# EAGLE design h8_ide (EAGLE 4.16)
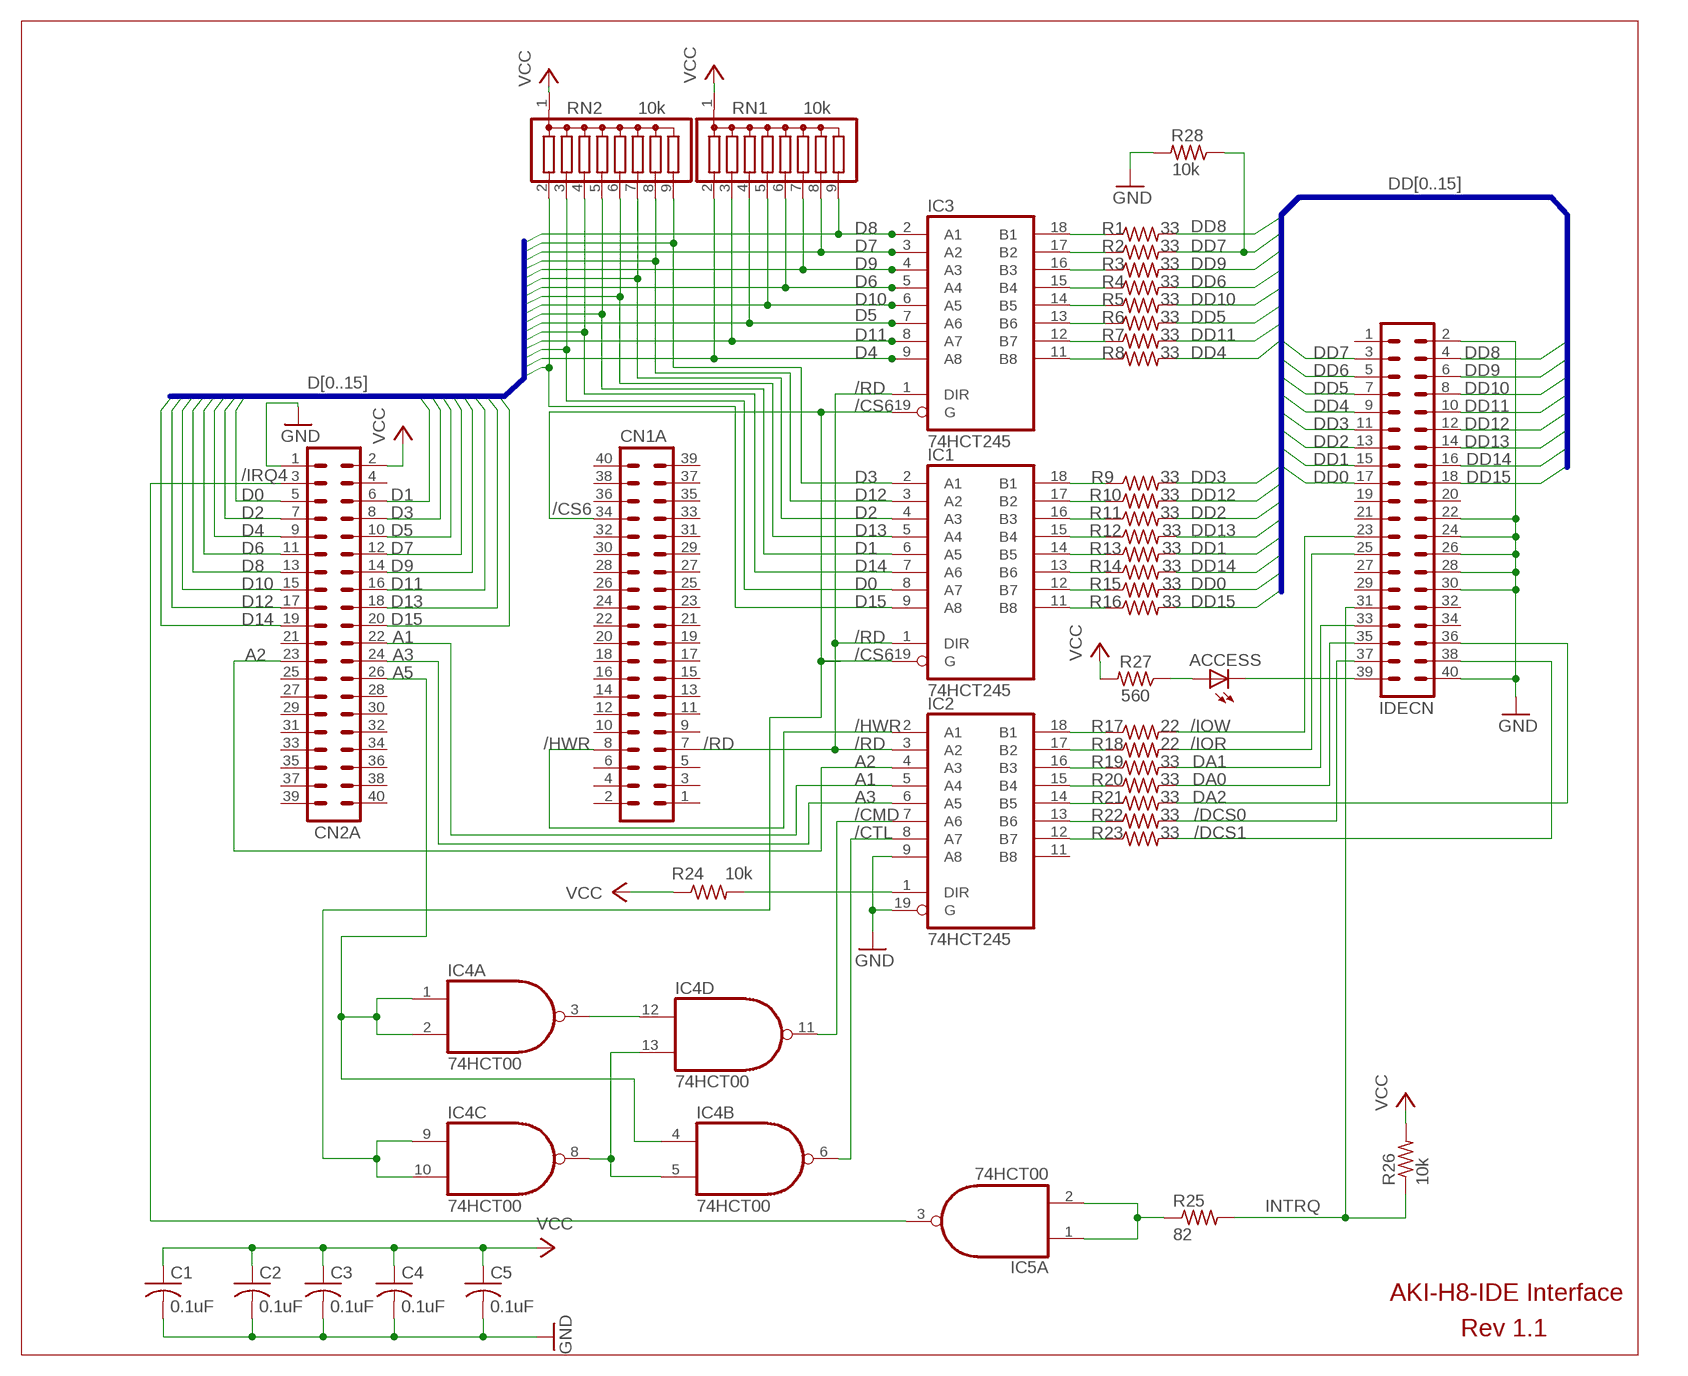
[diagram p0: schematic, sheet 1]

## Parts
ACCESS  LED3MM  [LED3MM]
C1  0.1uF  C-US025-024X044  [C025-024X044]
C2  0.1uF  C-US025-024X044  [C025-024X044]
C3  0.1uF  C-US025-024X044  [C025-024X044]
C4  0.1uF  C-US025-024X044  [C025-024X044]
C5  0.1uF  C-US025-024X044  [C025-024X044]
CN1A  MA20-2  [MA20-2]
CN2A  MA20-2  [MA20-2]
IC1  74HCT245  74LS245N  [DIL20]
IC2  74HCT245  74LS245N  [DIL20]
IC3  74HCT245  74LS245N  [DIL20]
IC4  74HCT00  7400N  [DIL14]
IC5  74HCT00  7400N  [DIL14]
IDECN  MA20-2  [MA20-2]
R1  33  R-US_0204/5  [0204/5]
R2  33  R-US_0204/5  [0204/5]
R3  33  R-US_0204/5  [0204/5]
R4  33  R-US_0204/5  [0204/5]
R5  33  R-US_0204/5  [0204/5]
R6  33  R-US_0204/5  [0204/5]
R7  33  R-US_0204/5  [0204/5]
R8  33  R-US_0204/5  [0204/5]
R9  33  R-US_0204/5  [0204/5]
R10  33  R-US_0204/5  [0204/5]
R11  33  R-US_0204/5  [0204/5]
R12  33  R-US_0204/5  [0204/5]
R13  33  R-US_0204/5  [0204/5]
R14  33  R-US_0204/5  [0204/5]
R15  33  R-US_0204/5  [0204/5]
R16  33  R-US_0204/5  [0204/5]
R17  22  R-US_0204/5  [0204/5]
R18  22  R-US_0204/5  [0204/5]
R19  33  R-US_0204/5  [0204/5]
R20  33  R-US_0204/5  [0204/5]
R21  33  R-US_0204/5  [0204/5]
R22  33  R-US_0204/5  [0204/5]
R23  33  R-US_0204/5  [0204/5]
R24  10k  R-US_0204/5  [0204/5]
R25  82  R-US_0204/5  [0204/5]
R26  10k  R-US_0204/5  [0204/5]
R27  560  R-US_0204/5  [0204/5]
R28  10k  R-US_0204/5  [0204/5]
RN1  10k  G08R  [SIL9]
RN2  10k  G08R  [SIL9]

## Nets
/CMD: IC2.7(A6) IC4.11(D:O)
/CS6: CN1A.34 IC1.19(G) IC3.19(G) IC4.9(C:I0) IC4.10(C:I1)
/CTL: IC2.8(A7) IC4.6(B:O)
/DCS0: IDECN.37 R22.2
/DCS1: IDECN.38 R23.2
/HWR: CN1A.8 IC2.2(A1)
/IOR: IDECN.25 R18.2
/IOW: IDECN.23 R17.2
/IRQ4: CN2A.3 IC5.3(A:O)
/RD: CN1A.7 IC1.1(DIR) IC2.3(A2) IC3.1(DIR)
A1: CN2A.22 IC2.5(A4)
A2: CN2A.23 IC2.4(A3)
A3: CN2A.24 IC2.6(A5)
A5: CN2A.26 IC4.1(A:I0) IC4.2(A:I1) IC4.4(B:I0)
D0: CN2A.5 IC1.8(A7) RN2.3
D1: CN2A.6 IC1.6(A5) RN2.5
D2: CN2A.7 IC1.4(A3) RN2.7
D3: CN2A.8 IC1.2(A1) RN2.9
D4: CN2A.9 IC3.9(A8) RN1.2
D5: CN2A.10 IC3.7(A6) RN1.4
D6: CN2A.11 IC3.5(A4) RN1.6
D7: CN2A.12 IC3.3(A2) RN1.8
D8: CN2A.13 IC3.2(A1) RN1.9
D9: CN2A.14 IC3.4(A3) RN1.7
D10: CN2A.15 IC3.6(A5) RN1.5
D11: CN2A.16 IC3.8(A7) RN1.3
D12: CN2A.17 IC1.3(A2) RN2.8
D13: CN2A.18 IC1.5(A4) RN2.6
D14: CN2A.19 IC1.7(A6) RN2.4
D15: CN2A.20 IC1.9(A8) RN2.2
DA0: IDECN.35 R20.2
DA1: IDECN.33 R19.2
DA2: IDECN.36 R21.2
DD0: IDECN.17 R15.2
DD1: IDECN.15 R13.2
DD2: IDECN.13 R11.2
DD3: IDECN.11 R9.2
DD4: IDECN.9 R8.2
DD5: IDECN.7 R6.2
DD6: IDECN.5 R4.2
DD7: IDECN.3 R2.2 R28.1
DD8: IDECN.4 R1.2
DD9: IDECN.6 R3.2
DD10: IDECN.8 R5.2
DD11: IDECN.10 R7.2
DD12: IDECN.12 R10.2
DD13: IDECN.14 R12.2
DD14: IDECN.16 R14.2
DD15: IDECN.18 R16.2
GND: C1.2 C2.2 C3.2 C4.2 C5.2 CN2A.1 IC2.9(A8) IC2.19(G) IDECN.2 IDECN.22 IDECN.24 IDECN.26 IDECN.28 IDECN.30 IDECN.40 R28.2
INTRQ: IDECN.31 R25.2 R26.1
N$1: IC3.18(B1) R1.1
N$2: IC3.17(B2) R2.1
N$3: IC3.16(B3) R3.1
N$4: IC3.15(B4) R4.1
N$5: IC3.14(B5) R5.1
N$6: IC3.13(B6) R6.1
N$7: IC3.12(B7) R7.1
N$8: IC3.11(B8) R8.1
N$9: IC1.18(B1) R9.1
N$10: IC1.17(B2) R10.1
N$11: IC1.16(B3) R11.1
N$12: IC1.15(B4) R12.1
N$13: IC1.14(B5) R13.1
N$14: IC1.13(B6) R14.1
N$15: IC1.12(B7) R15.1
N$16: IC1.11(B8) R16.1
N$17: IC2.18(B1) R17.1
N$18: IC2.17(B2) R18.1
N$19: IC2.16(B3) R19.1
N$20: IC2.15(B4) R20.1
N$21: IC2.14(B5) R21.1
N$22: IC2.13(B6) R22.1
N$23: IC2.12(B7) R23.1
N$26: ACCESS.K(C) IDECN.39
N$27: ACCESS.A R27.1
N$29: IC2.1(DIR) R24.2
N$30: IC4.5(B:I1) IC4.8(C:O) IC4.13(D:I1)
N$32: IC4.3(A:O) IC4.12(D:I0)
N$33: IC5.1(A:I0) IC5.2(A:I1) R25.1
VCC: C1.1 C2.1 C3.1 C4.1 C5.1 CN2A.2 R24.1 R26.2 R27.2 RN1.1 RN2.1
Unconnected: CN1A.1 CN1A.2 CN1A.3 CN1A.4 CN1A.5 CN1A.6 CN1A.9 CN1A.10 CN1A.11 CN1A.12 CN1A.13 CN1A.14 CN1A.15 CN1A.16 CN1A.17 CN1A.18 CN1A.19 CN1A.20 CN1A.21 CN1A.22 CN1A.23 CN1A.24 CN1A.25 CN1A.26 CN1A.27 CN1A.28 CN1A.29 CN1A.30 CN1A.31 CN1A.32 CN1A.33 CN1A.35 CN1A.36 CN1A.37 CN1A.38 CN1A.39 CN1A.40 CN2A.4 CN2A.21 CN2A.25 CN2A.27 CN2A.28 CN2A.29 CN2A.30 CN2A.31 CN2A.32 CN2A.33 CN2A.34 CN2A.35 CN2A.36 CN2A.37 CN2A.38 CN2A.39 CN2A.40 IC2.11(B8) IC5.4(B:I0) IC5.5(B:I1) IC5.6(B:O) IC5.8(C:O) IC5.9(C:I0) IC5.10(C:I1) IC5.11(D:O) IC5.12(D:I0) IC5.13(D:I1) IDECN.1 IDECN.19 IDECN.20 IDECN.21 IDECN.27 IDECN.29 IDECN.32 IDECN.34

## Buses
D[0..15]
DD[0..15]

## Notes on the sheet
- AKI-H8-IDE Interface
- Rev 1.1

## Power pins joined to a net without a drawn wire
GND: IC1.10(GND) IC2.10(GND) IC3.10(GND) IC4.7(P:GND) IC5.7(P:GND)
VCC: IC1.20(VCC) IC2.20(VCC) IC3.20(VCC) IC4.14(P:VCC) IC5.14(P:VCC)

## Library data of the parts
ACCESS = led:LED: LED
C1-C5 = rcl:C-US: CAPACITOR, American symbol
CN1A CN2A IDECN = con-lstb:MA20-2: PIN HEADER
IC1-IC3 = 74xx-us:74*245: Octal BUS TRANSCEIVER, 3-state
IC4 IC5 = 74xx-us:74*00: Quad 2-input NAND gate
R1-R28 = rcl:R-US_: RESISTOR, American symbol
RN1 RN2 = resistor-sil:G08R: SIL RESISTOR

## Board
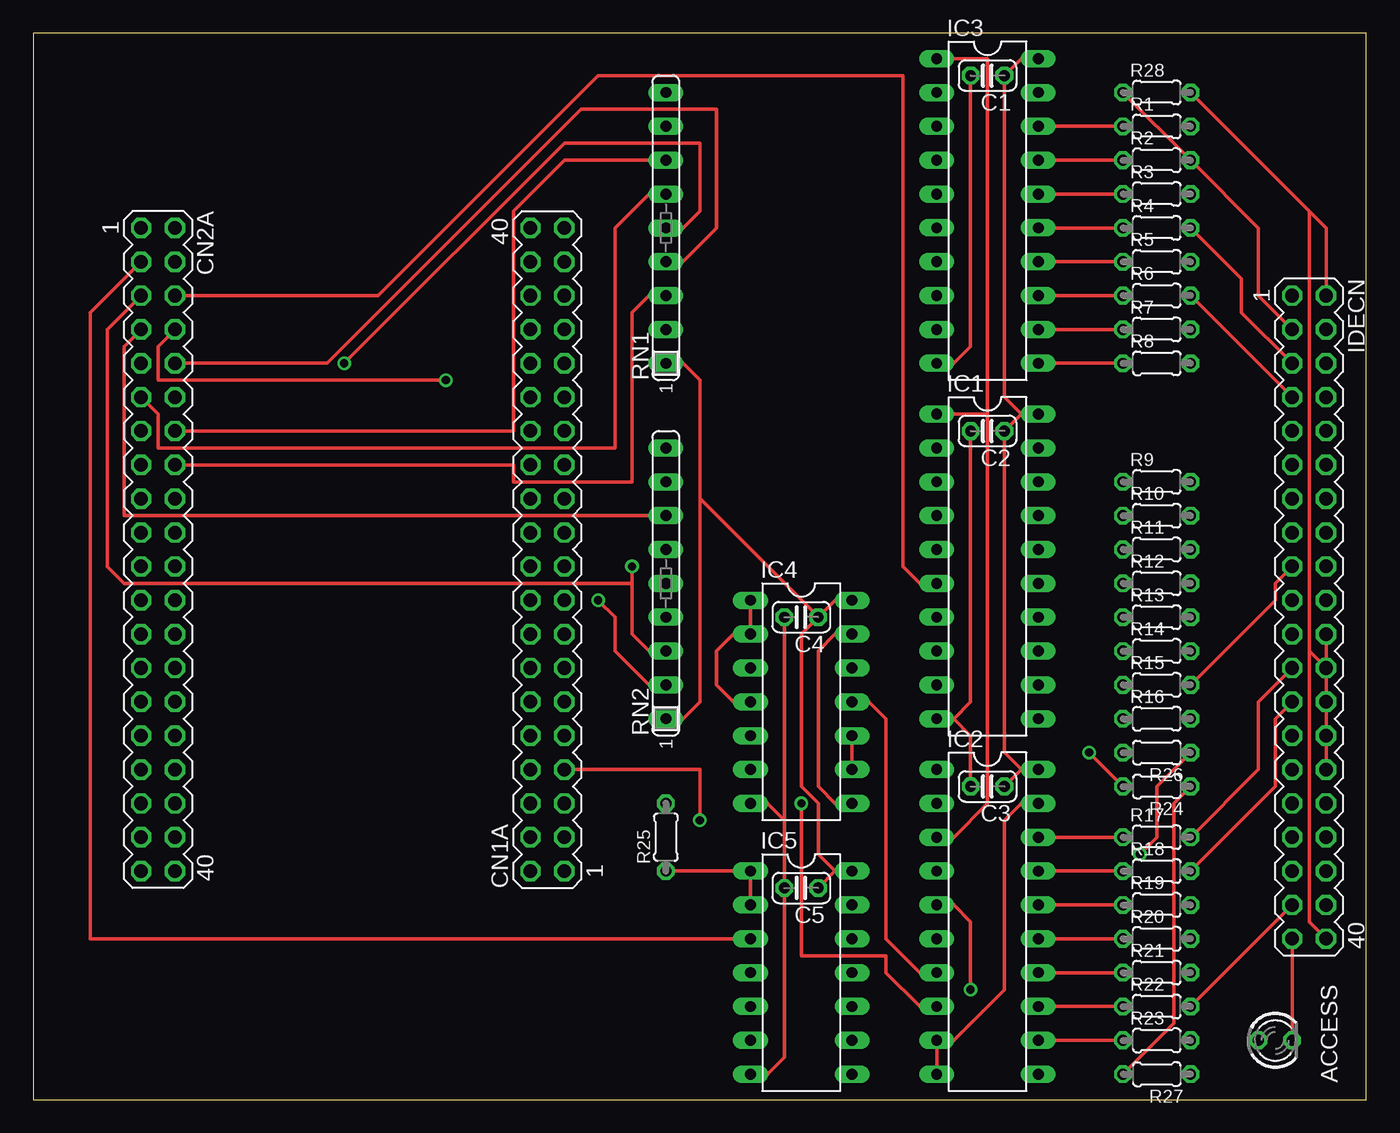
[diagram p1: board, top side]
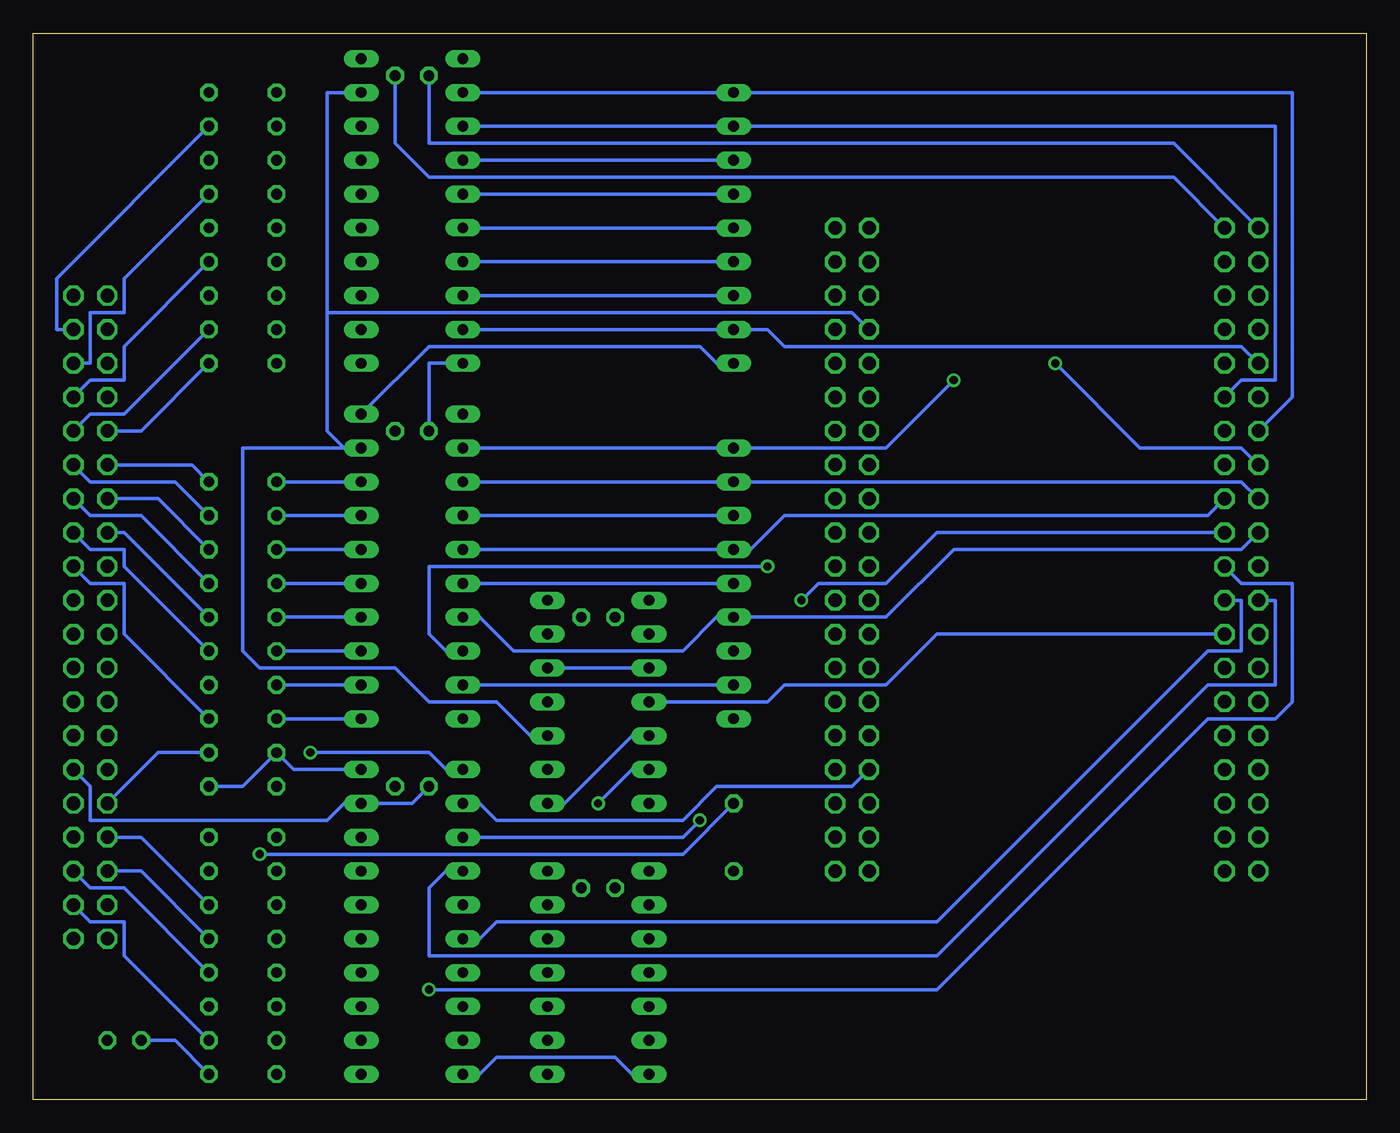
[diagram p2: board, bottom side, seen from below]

Size 100 x 80 mm. Coordinates in mm from the lower left corner, seen from the top.
Outline: 0,0 100,0 100,80 0,80 0,0
Copper layers (1*16): Top 0.035mm / dielectric 1.5mm / Bottom 0.035mm
Design rules "default": minimum track width 10mil, minimum drill 24mil, track to track 8mil, track to pad 8mil, pad to pad 8mil, via to via 8mil, smd to smd 8mil, copper to edge 40mil, drill to drill 8mil, minimum pad ring 10mil, minimum via ring 8mil, stop-mask expansion 4mil, vias tented up to drill 0mil, thermal gap 10mil

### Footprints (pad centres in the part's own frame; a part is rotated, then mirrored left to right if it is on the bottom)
LED3MM = drill 0.813 octagon: A -1.27,0; K 1.27,0
C025-024X044 = drill 0.813 octagon: 1 -1.27,0; 2 1.27,0
MA20-2 = drill 1.016 octagon: 1 -24.13,-1.27; 2 -24.13,1.27; 3 -21.59,-1.27; 4 -21.59,1.27; 5 -19.05,-1.27; 6 -19.05,1.27; 7 -16.51,-1.27; 8 -16.51,1.27; 9 -13.97,-1.27; 10 -13.97,1.27; 11 -11.43,-1.27; 12 -11.43,1.27; 13 -8.89,-1.27; 14 -8.89,1.27; 15 -6.35,-1.27; 16 -6.35,1.27; 17 -3.81,-1.27; 18 -3.81,1.27; 19 -1.27,-1.27; 20 -1.27,1.27; 21 1.27,-1.27; 22 1.27,1.27; 23 3.81,-1.27; 24 3.81,1.27; 25 6.35,-1.27; 26 6.35,1.27; 27 8.89,-1.27; 28 8.89,1.27; 29 11.43,-1.27; 30 11.43,1.27; 31 13.97,-1.27; 32 13.97,1.27; 33 16.51,-1.27; 34 16.51,1.27; 35 19.05,-1.27; 36 19.05,1.27; 37 21.59,-1.27; 38 21.59,1.27; 39 24.13,-1.27; 40 24.13,1.27
DIL20 = drill 0.813 long: 1 -11.43,-3.81; 2 -8.89,-3.81; 3 -6.35,-3.81; 4 -3.81,-3.81; 5 -1.27,-3.81; 6 1.27,-3.81; 7 3.81,-3.81; 8 6.35,-3.81; 9 8.89,-3.81; 10 11.43,-3.81; 11 11.43,3.81; 12 8.89,3.81; 13 6.35,3.81; 14 3.81,3.81; 15 1.27,3.81; 16 -1.27,3.81; 17 -3.81,3.81; 18 -6.35,3.81; 19 -8.89,3.81; 20 -11.43,3.81
DIL14 = drill 0.813 long: 1 -7.62,-3.81; 2 -5.08,-3.81; 3 -2.54,-3.81; 4 0,-3.81; 5 2.54,-3.81; 6 5.08,-3.81; 7 7.62,-3.81; 8 7.62,3.81; 9 5.08,3.81; 10 2.54,3.81; 11 0,3.81; 12 -2.54,3.81; 13 -5.08,3.81; 14 -7.62,3.81
0204/5 = drill 0.813 octagon: 1 -2.54,0; 2 2.54,0
SIL9 = drill 0.813 long: 1 -10.16,0; 2 -7.62,0; 3 -5.08,0; 4 -2.54,0; 5 0,0; 6 2.54,0; 7 5.08,0; 8 7.62,0; 9 10.16,0

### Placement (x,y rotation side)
ACCESS  93.18,4.44 0 top
C1  71.59,76.83 180 top
C2  71.59,50.16 180 top
C3  71.59,23.49 180 top
C4  57.62,36.19 180 top
C5  57.62,15.87 180 top
CN1A  38.57,41.27 90 top
CN2A  9.36,41.27 270 top
IC1  71.59,40 270 top
IC2  71.59,13.33 270 top
IC3  71.59,66.67 270 top
IC4  57.62,29.84 270 top
IC5  57.62,9.52 270 top
IDECN  95.72,36.19 270 top
R1  84.29,73.02 0 top
R2  84.29,70.48 0 top
R3  84.29,67.94 0 top
R4  84.29,65.4 0 top
R5  84.29,62.86 0 top
R6  84.29,60.32 0 top
R7  84.29,57.78 0 top
R8  84.29,55.24 0 top
R9  84.29,46.35 0 top
R10  84.29,43.81 0 top
R11  84.29,41.27 0 top
R12  84.29,38.73 0 top
R13  84.29,36.19 0 top
R14  84.29,33.65 0 top
R15  84.29,31.11 0 top
R16  84.29,28.57 0 top
R17  84.29,19.68 0 top
R18  84.29,17.14 0 top
R19  84.29,14.6 0 top
R20  84.29,12.06 0 top
R21  84.29,9.52 0 top
R22  84.29,6.98 0 top
R23  84.29,4.44 0 top
R24  84.29,23.49 180 top
R25  47.46,19.68 90 top
R26  84.29,26.03 180 top
R27  84.29,1.9 180 top
R28  84.29,75.56 0 top
RN1  47.46,65.4 90 top
RN2  47.46,38.73 90 top

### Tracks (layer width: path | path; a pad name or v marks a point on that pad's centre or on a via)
/CMD
  Top 0.254: IC2.7 66.51,9.52 63.97,12.06 63.97,28.57 62.7,29.84 IC4.11
/CS6
  Top 0.254: IC4.9 IC4.10
  Bottom 0.254: 76.67,48.89 77.94,50.16 77.94,59.05 | 77.94,59.05 77.94,75.56 IC3.19 | CN1A.34 38.57,59.05 77.94,59.05 | 76.67,48.89 84.29,48.89 84.29,33.65 83.02,32.38 72.86,32.38 70.32,29.84 65.24,29.84 62.7,27.3 IC4.10 | 76.67,48.89 IC1.19
/CTL  (via drill 0.61)
  Top 0.254: v57.62,22.22 57.62,10.79 63.97,10.79 63.97,9.52 66.51,6.98 IC2.8
  Bottom 0.254: v57.62,22.22 55.08,24.76 IC4.6
/DCS0
  Top 0.254: R22.2 IDECN.37
/DCS1
  Bottom 0.254: R23.2 93.18,10.79 93.18,13.33 95.72,13.33 IDECN.38
/HWR
  Bottom 0.254: CN1A.8 38.57,23.49 48.73,23.49 51.27,20.95 65.24,20.95 66.51,22.22 IC2.2
/IOR
  Top 0.254: R18.2 93.18,23.49 93.18,28.57 IDECN.25
/IOW
  Top 0.254: R17.2 91.91,24.76 91.91,29.84 IDECN.23
/IRQ4
  Top 0.254: CN2A.3 4.28,59.05 4.28,12.06 IC5.3
/RD  (via drill 0.61)
  Top 0.254: 71.59,51.43 71.59,22.22 69.05,19.68 IC2.3 | 71.59,51.43 IC1.1 | 71.59,51.43 71.59,78.1 IC3.1 | CN1A.7 50,24.76 v50,20.95
  Bottom 0.254: v50,20.95 51.27,19.68 IC2.3
A1  (via drill 0.61)
  Top 0.254: v70.32,8.25 70.32,13.33 69.05,14.6 IC2.5
  Bottom 0.254: v70.32,8.25 32.22,8.25 11.9,28.57 6.82,28.57 5.55,29.84 5.55,38.73 9.36,38.73 CN2A.22
A2
  Bottom 0.254: CN2A.23 6.82,37.46 6.82,31.11 11.9,31.11 32.22,10.79 70.32,10.79 70.32,15.87 69.05,17.14 IC2.4
A3
  Bottom 0.254: CN2A.24 9.36,37.46 9.36,33.65 11.9,33.65 32.22,13.33 65.24,13.33 66.51,12.06 IC2.6
A5
  Top 0.254: IC4.4 52.54,29.84 51.27,31.11 51.27,33.65 52.54,34.92 IC4.2 IC4.1
  Bottom 0.254: CN2A.26 32.22,34.92 36.03,31.11 43.65,31.11 44.92,29.84 IC4.4
D0  (via drill 0.61)
  Top 0.254: CN2A.5 5.55,57.78 5.55,40 6.82,38.73 44.92,38.73 | 44.92,38.73 44.92,34.92 46.19,33.65 RN2.3 | 44.92,38.73 v44.92,40
  Bottom 0.254: v44.92,40 70.32,40 70.32,34.92 69.05,33.65 IC1.8
D1
  Top 0.254: CN2A.6 25.87,60.32 42.38,76.83 65.24,76.83 65.24,40 66.51,38.73 IC1.6
  Bottom 0.254: IC1.6 RN2.5
D2
  Top 0.254: CN2A.7 6.82,56.51 6.82,43.81 RN2.7
  Bottom 0.254: RN2.7 IC1.4
D3  (via drill 0.61)
  Top 0.254: CN2A.8 9.36,56.51 9.36,53.97 v30.95,53.97
  Bottom 0.254: IC1.2 RN2.9 36.03,48.89 v30.95,53.97
D4
  Bottom 0.254: CN2A.9 9.36,56.51 43.65,56.51 44.92,57.78 RN1.2 IC3.9
D5
  Top 0.254: CN2A.10 22.06,55.24 41.11,74.29 51.27,74.29 51.27,65.4 48.73,62.86 RN1.4
  Bottom 0.254: RN1.4 IC3.7
D6
  Top 0.254: CN2A.11 9.36,51.43 9.36,48.89 43.65,48.89 43.65,65.4 46.19,67.94 RN1.6
  Bottom 0.254: RN1.6 IC3.5
D7
  Bottom 0.254: CN2A.12 9.36,53.97 6.82,53.97 6.82,73.02 RN1.8 IC3.3
D8
  Bottom 0.254: CN2A.13 5.55,52.7 5.55,75.56 RN1.9 IC3.2
D9
  Top 0.254: CN2A.14 36.03,50.16 36.03,66.67 39.84,70.48 RN1.7
  Bottom 0.254: RN1.7 IC3.4
D10  (via drill 0.61)
  Top 0.254: v23.33,55.24 39.84,71.75 50,71.75 50,66.67 48.73,65.4 RN1.5
  Bottom 0.254: RN1.5 IC3.6 | CN2A.15 9.36,48.89 16.98,48.89 v23.33,55.24
D11
  Top 0.254: CN2A.16 36.03,47.62 36.03,46.35 44.92,46.35 44.92,59.05 46.19,60.32 RN1.3
  Bottom 0.254: RN1.3 IC3.8
D12
  Bottom 0.254: CN2A.17 9.36,46.35 RN2.8 IC1.3
D13
  Bottom 0.254: CN2A.18 11.9,43.81 43.65,43.81 46.19,41.27 RN2.6 IC1.5
D14
  Bottom 0.254: IC1.7 66.51,36.19 63.97,33.65 51.27,33.65 48.73,36.19 RN2.4 36.03,36.19 30.95,41.27 9.36,41.27 CN2A.19
D15  (via drill 0.61)
  Top 0.254: v42.38,37.46 43.65,36.19 43.65,33.65 46.19,31.11 RN2.2
  Bottom 0.254: CN2A.20 32.22,42.54 36.03,38.73 41.11,38.73 v42.38,37.46 | RN2.2 IC1.9
DA0
  Bottom 0.254: R20.2 91.91,17.14 IDECN.35
DA1
  Bottom 0.254: R19.2 91.91,19.68 IDECN.33
DA2
  Bottom 0.254: R21.2 93.18,15.87 95.72,15.87 IDECN.36
DD0
  Top 0.254: R15.2 93.18,37.46 93.18,38.73 IDECN.17
DD1
  Bottom 0.254: R13.2 93.18,42.54 IDECN.15
DD2
  Bottom 0.254: R11.2 90.64,45.08 IDECN.13
DD3
  Bottom 0.254: R9.2 88.1,47.62 IDECN.11
DD4
  Bottom 0.254: R8.2 91.91,50.16 IDECN.9
DD5
  Top 0.254: IDECN.7 R6.2
DD6
  Top 0.254: R4.2 90.64,61.59 90.64,59.05 IDECN.5
DD7
  Top 0.254: R28.1 R2.2 91.91,65.4 91.91,60.32 IDECN.3
DD8
  Bottom 0.254: R1.2 98.26,61.59 98.26,57.78 IDECN.4
DD9
  Bottom 0.254: R3.2 93.18,61.59 93.18,59.05 95.72,59.05 95.72,55.24 IDECN.6
DD10
  Bottom 0.254: R5.2 93.18,56.51 93.18,53.97 95.72,53.97 IDECN.8
DD11
  Bottom 0.254: R7.2 93.18,51.43 95.72,51.43 IDECN.10
DD12
  Bottom 0.254: R10.2 89.37,46.35 95.72,46.35 IDECN.12
DD13
  Bottom 0.254: R12.2 91.91,43.81 95.72,43.81 IDECN.14
DD14
  Bottom 0.254: R14.2 93.18,40 93.18,41.27 95.72,41.27 IDECN.16
DD15
  Bottom 0.254: R16.2 93.18,34.92 93.18,38.73 95.72,38.73 IDECN.18
GND
  Top 0.254: IDECN.24 IDECN.22 | IDECN.30 IDECN.28 IDECN.26 IDECN.24 | 95.72,66.67 96.99,65.4 IDECN.2 | 95.72,66.67 R28.2 | IDECN.24 95.72,33.65 | 95.72,33.65 95.72,66.67 | IDECN.40 95.72,13.33 95.72,33.65 | IC2.10 IC2.9 69.05,4.44 72.86,8.25 72.86,20.95 74.13,22.22 IC2.19 | IC5.7 55.08,1.9 56.35,3.17 C5.2 56.35,20.95 | 56.35,20.95 55.08,22.22 IC4.7 | 56.35,20.95 C4.2 | 69.05,28.57 70.32,27.3 C3.2 | C1.2 70.32,56.51 69.05,55.24 IC3.10 | 69.05,28.57 70.32,29.84 C2.2 | 69.05,28.57 IC1.10
  Bottom 0.254: IC2.10 66.51,1.9 65.24,3.17 56.35,3.17 55.08,1.9 IC5.7 | C3.2 71.59,22.22 IC2.19 76.67,22.22 77.94,20.95 95.72,20.95 95.72,23.49 IDECN.30 | C2.2 70.32,55.24 IC3.10 | CN2A.1 14.44,71.75 70.32,71.75 C1.2
INTRQ  (via drill 0.61)
  Top 0.254: v83.02,18.41 84.29,19.68 84.29,23.49 R26.1
  Bottom 0.254: IDECN.31 90.64,26.03 R26.1 | R25.2 51.27,18.41 v83.02,18.41
N$1
  Top 0.254: IC3.18 R1.1
N$2
  Top 0.254: IC3.17 R2.1
N$3
  Top 0.254: IC3.16 R3.1
N$4
  Top 0.254: IC3.15 R4.1
N$5
  Top 0.254: IC3.14 R5.1
N$6
  Top 0.254: IC3.13 R6.1
N$7
  Top 0.254: IC3.12 R7.1
N$8
  Top 0.254: IC3.11 R8.1
N$9
  Bottom 0.254: IC1.18 R9.1
N$10
  Bottom 0.254: IC1.17 R10.1
N$11
  Bottom 0.254: IC1.16 R11.1
N$12
  Bottom 0.254: IC1.15 R12.1
N$13
  Bottom 0.254: IC1.14 R13.1
N$14
  Bottom 0.254: IC1.13 R14.1
N$15
  Bottom 0.254: IC1.12 R15.1
N$16
  Bottom 0.254: IC1.11 R16.1
N$17
  Top 0.254: IC2.18 R17.1
N$18
  Top 0.254: IC2.17 R18.1
N$19
  Top 0.254: IC2.16 R19.1
N$20
  Top 0.254: IC2.15 R20.1
N$21
  Top 0.254: IC2.14 R21.1
N$22
  Top 0.254: IC2.13 R22.1
N$23
  Top 0.254: IC2.12 R23.1
N$26
  Top 0.254: ACCESS.K IDECN.39
N$27
  Bottom 0.254: R27.1 89.37,4.44 ACCESS.A
N$29  (via drill 0.61)
  Top 0.254: v79.21,26.03 R24.2
  Bottom 0.254: v79.21,26.03 70.32,26.03 69.05,24.76 IC2.1
N$30
  Top 0.254: IC4.13 60.16,34.92 58.89,33.65 58.89,23.49 60.16,22.22 IC4.8
  Bottom 0.254: IC4.5 55.08,27.3 60.16,22.22 IC4.8
N$32
  Bottom 0.254: IC4.3 IC4.12
N$33
  Top 0.254: R25.1 IC5.1 IC5.2
VCC
  Top 0.254: C5.1 60.16,17.14 | C4.1 60.16,37.46 IC4.14 | 60.16,17.14 58.89,18.41 58.89,22.22 57.62,23.49 57.62,34.92 C4.1 | 60.16,17.14 IC5.14 | 50,45.08 50,53.97 48.73,55.24 RN1.1 | 50,45.08 50,29.84 48.73,28.57 RN2.1 | C4.1 50,45.08 | 74.13,24.76 C3.1 | R27.2 85.56,5.71 85.56,22.22 R24.1 | 74.13,51.43 C2.1 72.86,26.03 74.13,24.76 | IC3.20 74.13,78.1 C1.1 72.86,52.7 74.13,51.43 | IC1.20 74.13,51.43 | 74.13,24.76 IC2.20
  Bottom 0.254: IC2.20 80.48,24.76 R26.2 84.29,23.49 R24.1 | CN2A.2 14.44,69.21 70.32,69.21 72.86,71.75 C1.1 | IC1.20 70.32,56.51 50,56.51 48.73,55.24 RN1.1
